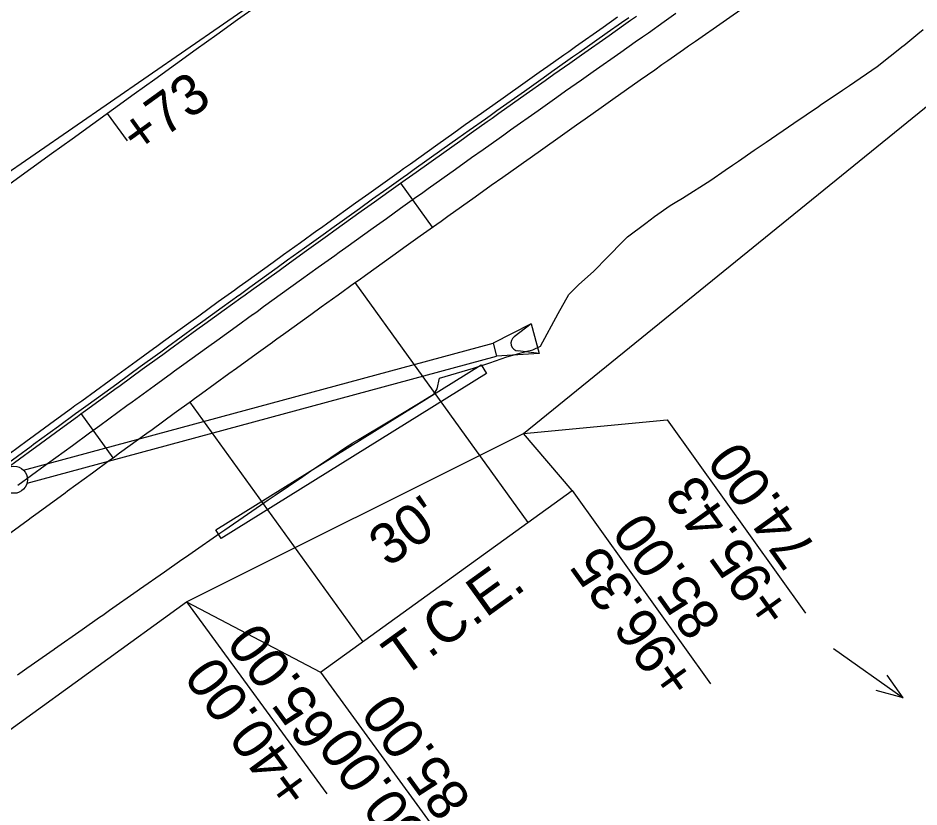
# Model space of a CAD drawing. Extents: x 1147550 to 1149124, y 2017436 to 2018779.
# Drawn here: x 1148099.8 to 1148232.5, y 2017798.5 to 2017914.6 of the extents above; entities that cross this region are included whole.
import ezdxf

# ---------------------------------------------------------------- set-up
doc = ezdxf.new("R2010")
doc.units = 0
for name, color, linetype in [('S_EDGE_CONCRETE', 7, 'Continuous'), ('S_ELECTRIC_UTILITIES', 7, 'Continuous'), ('S_HEADWALL', 7, 'Continuous'), ('S_IRON_PIN', 7, 'Continuous'), ('S_LANDSCAPING', 7, 'Continuous'), ('S_MAILBOX', 7, 'Continuous'), ('S_SECONDARY_CTL', 7, 'Continuous'), ('S_TANK', 7, 'Continuous'), ('S_TELEPHONE_UTILITIES', 7, 'Continuous'), ('S_TELEPHONE_UTILITIES_ANNOT', 7, 'Continuous')]:
    doc.layers.add(name, color=color, linetype=linetype)

msp = doc.modelspace()

# ---------------------------------------------------------------- linework, layer by layer
at = {"layer": 'S_EDGE_CONCRETE'}
msp.add_line((1148011.14, 2017831.73), (1148208.89, 2017968.31), dxfattribs=at)
msp.add_arc((1151464.82, 2013253.76), 5729.58, 124.62946, 129.43332, dxfattribs=at)
at = {"layer": 'S_ELECTRIC_UTILITIES'}
msp.add_lwpolyline([(1148174.25, 2017853.51), (1148195.39, 2017855.48), (1148215.76, 2017827.02)], dxfattribs=at)
at = {"layer": 'S_HEADWALL'}
for p, q in [((1148115.9, 2017896.55), (1148112.98, 2017900.61)), ((1148160.82, 2017883.85), (1148156.14, 2017890.34)), ((1148174.9, 2017840.4), (1148149.43, 2017875.71)), ((1148150.59, 2017822.83), (1148125.1, 2017858.16)), ((1148113.78, 2017849.92), (1148109.1, 2017856.41))]:
    msp.add_line(p, q, dxfattribs=at)
at = {"layer": 'S_IRON_PIN'}
for p, q in [((1148181.39, 2017845.09), (1148174.25, 2017853.51)), ((1148144.35, 2017818.38), (1148181.39, 2017845.09)), ((1148124.6, 2017828.73), (1148144.35, 2017818.38))]:
    msp.add_line(p, q, dxfattribs=at)
at = {"layer": 'S_LANDSCAPING'}
for points in [[(1148181.39, 2017845.09), (1148201.75, 2017816.62)], [(1148124.6, 2017828.73), (1148145.24, 2017800.46)], [(1148144.35, 2017818.38), (1148164.94, 2017790.07)]]:
    msp.add_lwpolyline(points, dxfattribs=at)
at = {"layer": 'S_MAILBOX'}
msp.add_lwpolyline([(1147623.68, 2017436.42), (1147751.67, 2017548.43), (1147958.55, 2017704.02), (1148020.45, 2017753.36), (1148124.6, 2017828.73), (1148174.25, 2017853.51), (1148282.74, 2017941.53), (1148421.63, 2018031.39), (1148612.18, 2018197.22), (1148639.91, 2018214.06), (1148753.45, 2018306.48), (1148799.03, 2018350.69)], dxfattribs=at)
at = {"layer": 'S_SECONDARY_CTL'}
msp.add_lwpolyline([(1148099.71, 2017817.98), (1148100.05, 2017818.23), (1148101.1, 2017818.96), (1148105.11, 2017821.76), (1148105.16, 2017821.79), (1148109.21, 2017824.63), (1148111.8, 2017826.45), (1148112.25, 2017826.77), (1148113.26, 2017827.48), (1148117.31, 2017830.32), (1148117.67, 2017830.56), (1148121.37, 2017833.15), (1148123.93, 2017834.93), (1148124.43, 2017835.28), (1148125.43, 2017835.98), (1148129.49, 2017838.8), (1148130.25, 2017839.33), (1148133.56, 2017841.63), (1148136.13, 2017843.39), (1148136.62, 2017843.72), (1148137.65, 2017844.42), (1148141.75, 2017847.18), (1148142.93, 2017847.98), (1148145.86, 2017849.95), (1148148.32, 2017851.61), (1148148.37, 2017851.64), (1148148.98, 2017852.05), (1148150.02, 2017852.64), (1148154.28, 2017855.19), (1148155.91, 2017856.19), (1148158.51, 2017857.77), (1148161.06, 2017859.33), (1148161.52, 2017860.04), (1148161.85, 2017861.61), (1148166.87, 2017863.1), (1148169.27, 2017863.87), (1148171.77, 2017864.75), (1148174.78, 2017865.59), (1148175.6, 2017865.82), (1148176.71, 2017866.33), (1148179.35, 2017871.15), (1148180.91, 2017873.94), (1148182.37, 2017875.44), (1148184.56, 2017877.34), (1148185.16, 2017877.98), (1148185.99, 2017878.88), (1148189.53, 2017882.45), (1148192.24, 2017884.47), (1148193.5, 2017885.41), (1148195.84, 2017887.03), (1148196.58, 2017887.5), (1148197.62, 2017888.15), (1148201.8, 2017890.8), (1148203.94, 2017892.26), (1148205, 2017892.99), (1148205.89, 2017893.59), (1148208.21, 2017895.18), (1148208.94, 2017895.68), (1148209.97, 2017896.38), (1148214.05, 2017899.19), (1148217.66, 2017901.64), (1148218.14, 2017901.97), (1148220.43, 2017903.51), (1148221.2, 2017904.03), (1148222.25, 2017904.73), (1148226.33, 2017907.53), (1148230.15, 2017910.54), (1148230.23, 2017910.6), (1148232.31, 2017912.31), (1148233.07, 2017912.94)], dxfattribs=at)
at = {"layer": 'S_TANK'}
for p, q in [((1148219.88, 2017821.84), (1148230.13, 2017814.58)), ((1148230.13, 2017814.58), (1148227.8, 2017817.94)), ((1148230.13, 2017814.58), (1148226.18, 2017815.66))]:
    msp.add_line(p, q, dxfattribs=at)
at = {"layer": 'S_TELEPHONE_UTILITIES'}
for points in [[(1148098.73, 2017838.91), (1148101.28, 2017840.79), (1148101.74, 2017841.12), (1148102.73, 2017841.85), (1148106.73, 2017844.78), (1148107.09, 2017845.03), (1148110.74, 2017847.71), (1148113.27, 2017849.55), (1148113.77, 2017849.91), (1148114.75, 2017850.63), (1148118.77, 2017853.55), (1148119.52, 2017854.1), (1148122.78, 2017856.47), (1148125.31, 2017858.31), (1148125.79, 2017858.65), (1148126.8, 2017859.39), (1148130.82, 2017862.3), (1148131.97, 2017863.13), (1148134.84, 2017865.21), (1148137.26, 2017866.95), (1148137.3, 2017866.98), (1148137.9, 2017867.42), (1148138.87, 2017868.11), (1148142.9, 2017871.01), (1148144.45, 2017872.13), (1148146.93, 2017873.91), (1148149.35, 2017875.65), (1148150, 2017876.11), (1148150.96, 2017876.8), (1148154.99, 2017879.69), (1148156.95, 2017881.09), (1148159.03, 2017882.58), (1148161.44, 2017884.3), (1148162.09, 2017884.76), (1148163.07, 2017885.46), (1148167.12, 2017888.34), (1148169.48, 2017890.02), (1148171.16, 2017891.22), (1148173.53, 2017892.89), (1148174.23, 2017893.39), (1148175.21, 2017894.09), (1148179.26, 2017896.96), (1148182.03, 2017898.92), (1148183.31, 2017899.82), (1148185.65, 2017901.47), (1148186.36, 2017901.98), (1148187.37, 2017902.69), (1148191.43, 2017905.54), (1148193.55, 2017907.04), (1148194.61, 2017907.78), (1148195.49, 2017908.4), (1148197.79, 2017910.02), (1148198.52, 2017910.53), (1148199.55, 2017911.25), (1148203.62, 2017914.1), (1148207.21, 2017916.61)], [(1148097.11, 2017849.51), (1148101.13, 2017852.45), (1148101.48, 2017852.7), (1148105.14, 2017855.38), (1148107.67, 2017857.23), (1148108.17, 2017857.59), (1148109.16, 2017858.31), (1148113.18, 2017861.24), (1148113.93, 2017861.78), (1148117.2, 2017864.16), (1148119.73, 2017866), (1148120.21, 2017866.34), (1148121.22, 2017867.08), (1148125.25, 2017869.99), (1148126.4, 2017870.83), (1148129.28, 2017872.91), (1148131.7, 2017874.65), (1148131.74, 2017874.68), (1148132.35, 2017875.12), (1148133.31, 2017875.82), (1148137.35, 2017878.72), (1148138.9, 2017879.84), (1148141.38, 2017881.62), (1148143.81, 2017883.37), (1148144.46, 2017883.83), (1148145.42, 2017884.52), (1148149.47, 2017887.42), (1148151.43, 2017888.82), (1148153.51, 2017890.31), (1148155.92, 2017892.03), (1148156.57, 2017892.49), (1148157.56, 2017893.2), (1148161.61, 2017896.08), (1148163.98, 2017897.76), (1148165.66, 2017898.96), (1148168.03, 2017900.64), (1148168.73, 2017901.14), (1148169.72, 2017901.84), (1148173.77, 2017904.71), (1148176.55, 2017906.67), (1148177.83, 2017907.58), (1148180.17, 2017909.23), (1148180.89, 2017909.74), (1148181.9, 2017910.45), (1148185.96, 2017913.31), (1148188.09, 2017914.81)], [(1148097.71, 2017848.7), (1148101.72, 2017851.64), (1148102.07, 2017851.9), (1148105.73, 2017854.57), (1148108.26, 2017856.42), (1148108.76, 2017856.78), (1148109.75, 2017857.5), (1148113.77, 2017860.43), (1148114.52, 2017860.97), (1148117.79, 2017863.35), (1148120.32, 2017865.19), (1148120.8, 2017865.53), (1148121.81, 2017866.27), (1148125.84, 2017869.18), (1148126.99, 2017870.02), (1148129.87, 2017872.1), (1148132.28, 2017873.84), (1148132.33, 2017873.87), (1148132.93, 2017874.31), (1148133.9, 2017875.01), (1148137.93, 2017877.91), (1148139.49, 2017879.03), (1148141.97, 2017880.81), (1148144.4, 2017882.56), (1148145.05, 2017883.02), (1148146.01, 2017883.71), (1148150.05, 2017886.6), (1148152.01, 2017888.01), (1148154.09, 2017889.49), (1148156.5, 2017891.22), (1148157.16, 2017891.68), (1148158.14, 2017892.38), (1148162.19, 2017895.27), (1148164.55, 2017896.95), (1148166.24, 2017898.15), (1148168.61, 2017899.83), (1148169.31, 2017900.32), (1148170.29, 2017901.02), (1148174.35, 2017903.9), (1148177.13, 2017905.86), (1148178.41, 2017906.77), (1148180.75, 2017908.42), (1148181.46, 2017908.92), (1148182.47, 2017909.63), (1148186.54, 2017912.5), (1148188.66, 2017913.99), (1148189.72, 2017914.73)], [(1148098, 2017848.3), (1148102.01, 2017851.23), (1148102.36, 2017851.49), (1148106.02, 2017854.17), (1148108.55, 2017856.01), (1148109.05, 2017856.38), (1148110.04, 2017857.1), (1148114.06, 2017860.02), (1148114.81, 2017860.57), (1148118.08, 2017862.95), (1148120.61, 2017864.78), (1148121.09, 2017865.13), (1148122.1, 2017865.86), (1148126.13, 2017868.78), (1148127.28, 2017869.61), (1148130.16, 2017871.69), (1148132.58, 2017873.44), (1148132.62, 2017873.47), (1148133.23, 2017873.9), (1148134.19, 2017874.6), (1148138.22, 2017877.5), (1148139.78, 2017878.62), (1148142.26, 2017880.41), (1148144.69, 2017882.15), (1148145.34, 2017882.61), (1148146.3, 2017883.3), (1148150.34, 2017886.2), (1148152.3, 2017887.6), (1148154.38, 2017889.09), (1148156.8, 2017890.81), (1148157.45, 2017891.27), (1148158.43, 2017891.98), (1148162.48, 2017894.86), (1148164.84, 2017896.54), (1148166.53, 2017897.74), (1148168.9, 2017899.42), (1148169.6, 2017899.92), (1148170.58, 2017900.62), (1148174.64, 2017903.49), (1148177.41, 2017905.45), (1148178.7, 2017906.36), (1148181.04, 2017908.01), (1148181.75, 2017908.51), (1148182.76, 2017909.22), (1148186.82, 2017912.09), (1148188.95, 2017913.58), (1148190.01, 2017914.32), (1148190.89, 2017914.94)], [(1148099.77, 2017845.88), (1148103.78, 2017848.81), (1148104.13, 2017849.07), (1148107.79, 2017851.74), (1148110.32, 2017853.59), (1148110.82, 2017853.95), (1148111.81, 2017854.67), (1148115.82, 2017857.6), (1148116.58, 2017858.14), (1148119.84, 2017860.52), (1148122.38, 2017862.36), (1148122.85, 2017862.7), (1148123.86, 2017863.44), (1148127.89, 2017866.35), (1148129.04, 2017867.18), (1148131.91, 2017869.26), (1148134.33, 2017871), (1148134.38, 2017871.03), (1148134.98, 2017871.47), (1148135.94, 2017872.17), (1148139.98, 2017875.07), (1148141.53, 2017876.19), (1148144.01, 2017877.97), (1148146.44, 2017879.71), (1148147.09, 2017880.18), (1148148.05, 2017880.86), (1148152.09, 2017883.76), (1148154.04, 2017885.16), (1148156.13, 2017886.65), (1148158.54, 2017888.37), (1148159.19, 2017888.83), (1148160.17, 2017889.53), (1148164.22, 2017892.41), (1148166.58, 2017894.1), (1148168.27, 2017895.29), (1148170.63, 2017896.97), (1148171.33, 2017897.47), (1148172.32, 2017898.17), (1148176.37, 2017901.04), (1148179.15, 2017903), (1148180.43, 2017903.91), (1148182.77, 2017905.56), (1148183.48, 2017906.06), (1148184.49, 2017906.77), (1148188.55, 2017909.63), (1148190.68, 2017911.13), (1148191.73, 2017911.87), (1148192.62, 2017912.49), (1148194.92, 2017914.11), (1148195.65, 2017914.62), (1148196.68, 2017915.34)]]:
    msp.add_lwpolyline(points, dxfattribs=at)
at = {"layer": 'S_TELEPHONE_UTILITIES_ANNOT'}
for p, q in [((1148175.34, 2017869.61), (1148169.75, 2017866.8)), ((1148175.34, 2017869.61), (1148172.85, 2017867.73)), ((1148175.34, 2017869.61), (1148176.51, 2017865.26)), ((1148100.59, 2017848.1), (1148169.75, 2017866.8)), ((1148169.75, 2017866.8), (1148170.27, 2017864.87)), ((1148176.51, 2017865.26), (1148173.37, 2017865.64)), ((1148101.12, 2017846.17), (1148170.27, 2017864.87)), ((1148176.51, 2017865.26), (1148170.27, 2017864.87))]:
    msp.add_line(p, q, dxfattribs=at)
msp.add_lwpolyline([(1148128.92, 2017839.3), (1148167.98, 2017863.6), (1148168.77, 2017862.32), (1148129.71, 2017838.02)], close=True, dxfattribs=at)
msp.add_circle((1148099.18, 2017846.69), 2, dxfattribs=at)
msp.add_arc((1148173.55, 2017866.8), 1.17, 127.0908, 264.9243, dxfattribs=at)

# ---------------------------------------------------------------- texts
at = {"layer": 'S_ELECTRIC_UTILITIES'}
for s, p in [('74.00', (1148217.62, 2017836.45)), ('+95.43', (1148214.06, 2017827.67))]:
    msp.add_text(s, height=6, rotation=125.5792, dxfattribs=at).set_placement(p)
at = {"layer": 'S_HEADWALL'}
for s, p in [('+73', (1148117.54, 2017894.28)), ("30'", (1148154.3, 2017833.69))]:
    msp.add_text(s, height=6, rotation=35.8035, dxfattribs=at).set_placement(p)
at = {"layer": 'S_IRON_PIN'}
msp.add_text('T.C.E.', height=6, rotation=35.8017, dxfattribs=at).set_placement((1148156.38, 2017817.43))
at = {"layer": 'S_LANDSCAPING'}
for s, rotation, p in [('85.00', 125.57, (1148203.61, 2017826.05)), ('+96.35', 125.57, (1148200.05, 2017817.28)), ('65.00', 126.1335, (1148147, 2017809.91)), ('+40.00', 126.1335, (1148143.49, 2017801.15)), ('85.00', 126.0335, (1148166.73, 2017799.52)), ('+50.00', 126.0335, (1148163.2, 2017790.77))]:
    msp.add_text(s, height=6, rotation=rotation, dxfattribs=at).set_placement(p)

doc.saveas('drawing.dxf')
